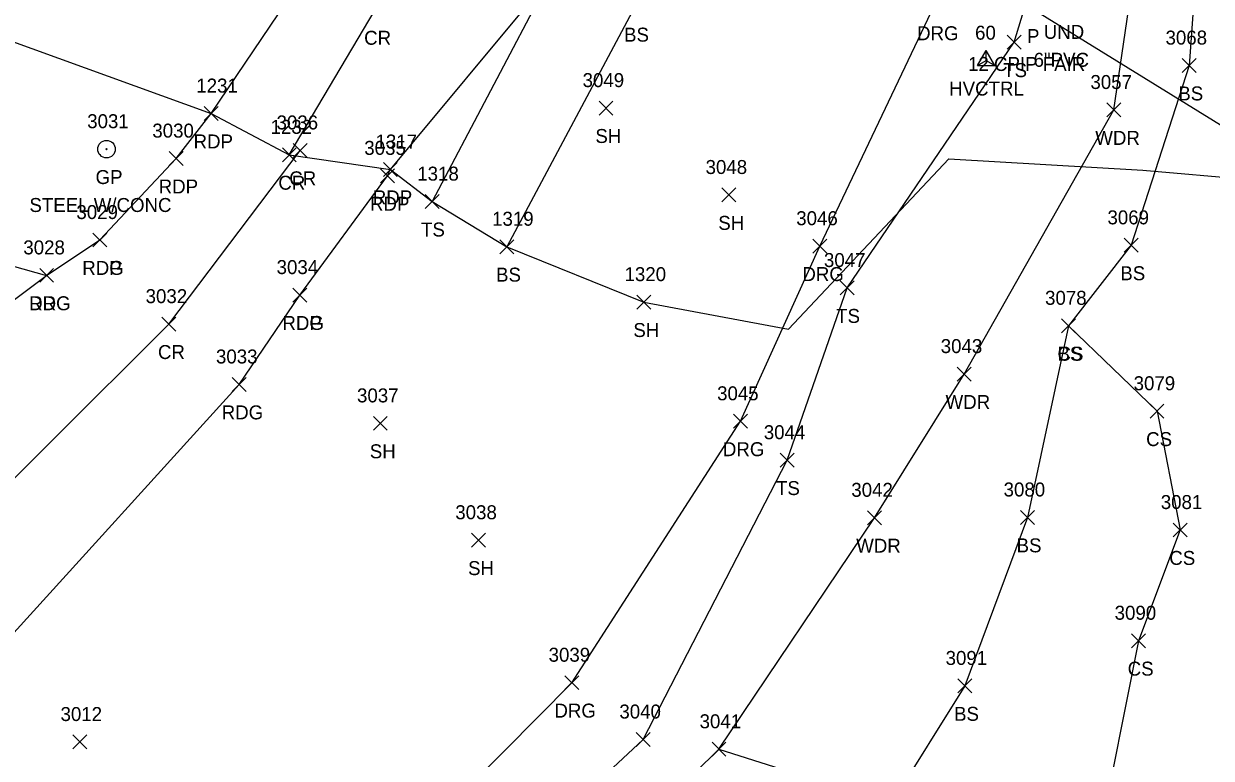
# Model space of a CAD drawing. Extents: x 49137 to 50946, y 9590 to 10709.
# Drawn here: x 49915 to 50085.1, y 9701 to 9806.1 of the extents above; entities that cross this region are included whole.
import ezdxf

# ---------------------------------------------------------------- set-up
doc = ezdxf.new("R2010")
doc.units = 0
for name, color, linetype in [('C_A', 7, 'Continuous'), ('C_I', 7, 'Continuous'), ('CPSM', 7, 'Continuous'), ('D_A', 7, 'Continuous'), ('D_C', 7, 'Continuous'), ('DCP', 7, 'Continuous'), ('L_A', 7, 'Continuous'), ('L_I', 7, 'Continuous'), ('L_TIC', 7, 'Continuous'), ('LAWA', 7, 'Continuous'), ('LELB', 7, 'Continuous'), ('LSOGP', 7, 'Continuous'), ('P_A', 7, 'Continuous'), ('P_I', 7, 'Continuous'), ('P_TIC', 7, 'Continuous'), ('PET', 7, 'Continuous'), ('PEU', 7, 'Continuous'), ('PRC', 7, 'Continuous'), ('R_A', 7, 'Continuous'), ('R_C', 7, 'Continuous'), ('R_I', 7, 'Continuous'), ('R_TIC', 7, 'Continuous'), ('RDG', 7, 'Continuous'), ('RGP', 7, 'Continuous')]:
    doc.layers.add(name, color=color, linetype=linetype)

msp = doc.modelspace()

# ---------------------------------------------------------------- linework, layer by layer
at = {"layer": 'CPSM'}
for p, q in [((50051.61, 9800.13), (50052.86, 9802.3)), ((50054.11, 9800.13), (50052.86, 9802.3)), ((50052.87, 9800.85), (50052.86, 9802.3)), ((50051.61, 9800.13), (50052.87, 9800.85)), ((50052.87, 9800.85), (50052.87, 9800.85)), ((50052.87, 9800.85), (50054.11, 9800.13)), ((50051.61, 9800.13), (50054.11, 9800.13))]:
    msp.add_line(p, q, dxfattribs=at)
at = {"layer": 'DCP'}
msp.add_lwpolyline([(49941.69, 9827.48), (50059.34, 9808.37), (50181.4, 9733.09), (50281.74, 9743.29), (50422.72, 9892.52), (50122.34, 10663.61), (50179.93, 10552.61), (50179.64, 10394.45), (50122.34, 10285.07), (50121.56, 10284.35)], dxfattribs=at)
at = {"layer": 'L_TIC'}
for points in [[(50055.89, 9802.49), (50057.89, 9804.49)], [(50057.89, 9802.49), (50055.89, 9804.49)], [(50080.95, 9799.15), (50082.95, 9801.15)], [(50082.95, 9799.15), (50080.95, 9801.15)], [(49997.39, 9793.06), (49999.39, 9795.06)], [(49999.39, 9793.06), (49997.39, 9795.06)], [(50070.14, 9792.79), (50072.14, 9794.79)], [(50072.14, 9792.79), (50070.14, 9794.79)], [(49972.48, 9779.67), (49974.48, 9781.67)], [(49974.48, 9779.67), (49972.48, 9781.67)], [(50015, 9780.62), (50017, 9782.62)], [(50017, 9780.62), (50015, 9782.62)], [(49983.2, 9773.21), (49985.2, 9775.21)], [(49985.2, 9773.21), (49983.2, 9775.21)], [(50072.64, 9773.41), (50074.64, 9775.41)], [(50074.64, 9773.41), (50072.64, 9775.41)], [(50031.96, 9767.3), (50033.96, 9769.3)], [(50033.96, 9767.3), (50031.96, 9769.3)], [(50002.82, 9765.28), (50004.82, 9767.28)], [(50004.82, 9765.28), (50002.82, 9767.28)], [(50063.64, 9761.89), (50065.64, 9763.89)], [(50065.64, 9761.89), (50063.64, 9763.89)], [(50063.64, 9761.89), (50065.64, 9763.89)], [(50065.64, 9761.89), (50063.64, 9763.89)], [(50048.69, 9754.98), (50050.69, 9756.98)], [(50050.69, 9754.98), (50048.69, 9756.98)], [(50076.34, 9749.66), (50078.34, 9751.66)], [(50078.34, 9749.66), (50076.34, 9751.66)], [(49965.06, 9747.92), (49967.06, 9749.92)], [(49967.06, 9747.92), (49965.06, 9749.92)], [(50023.34, 9742.65), (50025.34, 9744.65)], [(50025.34, 9742.65), (50023.34, 9744.65)], [(50035.88, 9734.4), (50037.88, 9736.4)], [(50037.88, 9734.4), (50035.88, 9736.4)], [(50057.78, 9734.45), (50059.78, 9736.45)], [(50059.78, 9734.45), (50057.78, 9736.45)], [(50079.65, 9732.65), (50081.65, 9734.65)], [(50081.65, 9732.65), (50079.65, 9734.65)], [(49979.14, 9731.19), (49981.14, 9733.19)], [(49981.14, 9731.19), (49979.14, 9733.19)], [(50073.7, 9716.8), (50075.7, 9718.8)], [(50075.7, 9716.8), (50073.7, 9718.8)], [(50048.82, 9710.33), (50050.82, 9712.33)], [(50050.82, 9710.33), (50048.82, 9712.33)], [(49922.01, 9702.3), (49924.01, 9704.3)], [(49924.01, 9702.3), (49922.01, 9704.3)], [(50002.73, 9702.66), (50004.73, 9704.66)], [(50004.73, 9702.66), (50002.73, 9704.66)], [(50013.58, 9701.26), (50015.58, 9703.26)], [(50015.58, 9701.26), (50013.58, 9703.26)], [(50013.58, 9701.26), (50015.58, 9703.26)], [(50015.58, 9701.26), (50013.58, 9703.26)], [(50013.58, 9701.26), (50015.58, 9703.26)], [(50015.58, 9701.26), (50013.58, 9703.26)]]:
    msp.add_lwpolyline(points, dxfattribs=at)
at = {"layer": 'LAWA'}
for points in [[(50014.58, 9702.26), (50036.88, 9735.4), (50049.69, 9755.98), (50071.14, 9793.79), (50075.59, 9824.01)], [(50014.58, 9702.26), (50039.25, 9694.43), (50057.47, 9686.03), (50059.19, 9683.38), (50066.6, 9684.8), (50067.1, 9678.81), (50060, 9674.6), (50065.38, 9669.03), (50074.52, 9675.19), (50088.42, 9676.7), (50096.85, 9701.02)]]:
    msp.add_lwpolyline(points, dxfattribs=at)
at = {"layer": 'LELB'}
for points in [[(49989.55, 9904), (49994.55, 9892.66), (49998.25, 9866.29), (49993.74, 9835.93), (49990.22, 9812.41), (49973.48, 9780.67)], [(49989.55, 9904), (50004.44, 9895.83), (50014.35, 9868.49), (50005.81, 9838.02), (50002.54, 9808.57), (49984.2, 9774.21)], [(49918.74, 9626.48), (49955.93, 9659.04), (50003.73, 9703.66), (50024.34, 9743.65), (50032.96, 9768.3), (50056.89, 9803.49), (50065.96, 9833.31)], [(50083.49, 9821.5), (50081.95, 9800.15), (50073.64, 9774.41), (50064.64, 9762.89), (50058.78, 9735.45), (50049.82, 9711.33), (50039.25, 9694.43), (50032.02, 9676.72), (50013.68, 9661.38), (49987.38, 9644.23), (49938.8, 9613.7)], [(50064.64, 9762.89), (50077.34, 9750.66), (50080.65, 9733.65), (50074.7, 9717.8), (50068.89, 9688.77)], [(49927.18, 9621.5), (49962.52, 9650.98), (50014.58, 9702.26)]]:
    msp.add_lwpolyline(points, dxfattribs=at)
at = {"layer": 'LSOGP'}
msp.add_lwpolyline([(49755.15, 9779.76), (49800.92, 9796.37), (49846.88, 9798.73), (49883.29, 9814.53), (49941.82, 9793.29), (49953.02, 9787.37), (49967.5, 9785.27), (49973.48, 9780.68), (49984.2, 9774.21), (50003.83, 9766.28), (50024.54, 9762.42), (50047.5, 9786.77), (50075.33, 9785.18), (50090.63, 9783.84), (50104.73, 9771.51), (50112.8, 9763.41), (50118.43, 9787.61), (50123.54, 9809.37), (50149.22, 9831.22), (50159.79, 9836.35), (50172.36, 9837.78), (50185.48, 9838.52)], dxfattribs=at)
at = {"layer": 'P_TIC'}
for points in [[(49940.82, 9792.28), (49942.82, 9794.28)], [(49942.82, 9792.28), (49940.82, 9794.28)], [(49952.02, 9786.37), (49954.02, 9788.37)], [(49954.02, 9786.37), (49952.02, 9788.37)], [(49953.58, 9787), (49955.58, 9789)], [(49955.58, 9787), (49953.58, 9789)], [(49935.81, 9785.83), (49937.81, 9787.83)], [(49937.81, 9785.83), (49935.81, 9787.83)], [(49966.1, 9783.36), (49968.1, 9785.36)], [(49968.1, 9783.36), (49966.1, 9785.36)], [(49966.49, 9784.27), (49968.49, 9786.27)], [(49968.49, 9784.27), (49966.49, 9786.27)], [(49924.86, 9774.17), (49926.86, 9776.17)], [(49926.86, 9774.17), (49924.86, 9776.17)], [(49924.86, 9774.17), (49926.86, 9776.17)], [(49926.86, 9774.17), (49924.86, 9776.17)], [(49917.25, 9769.11), (49919.25, 9771.11)], [(49919.25, 9769.11), (49917.25, 9771.11)], [(49953.54, 9766.29), (49955.54, 9768.29)], [(49955.54, 9766.29), (49953.54, 9768.29)], [(49953.54, 9766.29), (49955.54, 9768.29)], [(49955.54, 9766.29), (49953.54, 9768.29)], [(49934.77, 9762.13), (49936.77, 9764.13)], [(49936.77, 9762.13), (49934.77, 9764.13)], [(49944.85, 9753.49), (49946.85, 9755.49)], [(49946.85, 9753.49), (49944.85, 9755.49)]]:
    msp.add_lwpolyline(points, dxfattribs=at)
at = {"layer": 'PET'}
for points in [[(49941.82, 9793.28), (49956.36, 9814.79), (49966.07, 9820.11), (49965.86, 9838.81), (49966.08, 9865), (49966, 9911.87), (49965.71, 9947.75), (49965.49, 9981.09), (49977.22, 9981.69), (49989.03, 9982.19), (49989.41, 9973.23), (49989.05, 9951.58), (49989.55, 9915.93), (49989.55, 9904), (49989.7, 9866.37), (49989.32, 9838.09), (49989.1, 9811.29), (49967.49, 9785.27)], [(49936.81, 9786.83), (49941.82, 9793.28)], [(49925.86, 9775.17), (49936.81, 9786.83)], [(49967.1, 9784.36), (49967.49, 9785.27)], [(49954.54, 9767.29), (49967.1, 9784.36)]]:
    msp.add_lwpolyline(points, dxfattribs=at)
at = {"layer": 'PEU'}
for points in [[(49842.28, 9718.62), (49887.62, 9747.17), (49918.25, 9770.11), (49925.86, 9775.17)], [(49862.34, 9689.85), (49911.69, 9716.87), (49945.85, 9754.49), (49954.54, 9767.29)]]:
    msp.add_lwpolyline(points, dxfattribs=at)
at = {"layer": 'PRC'}
for points in [[(49953.02, 9787.37), (49965.31, 9808.12), (49973.95, 9825.62), (49977.78, 9849.57), (49977.72, 9864.78), (49978.39, 9912), (49976.86, 9948.04), (49977.22, 9981.69)], [(49852.15, 9703.48), (49901.8, 9729.33), (49935.77, 9763.13), (49954.58, 9788)]]:
    msp.add_lwpolyline(points, dxfattribs=at)
at = {"layer": 'R_TIC'}
for points in [[(50028.04, 9773.29), (50030.04, 9775.29)], [(50030.04, 9773.29), (50028.04, 9775.29)], [(49917.25, 9769.11), (49919.25, 9771.11)], [(49919.25, 9769.11), (49917.25, 9771.11)], [(50016.65, 9748.22), (50018.65, 9750.22)], [(50018.65, 9748.22), (50016.65, 9750.22)], [(49992.51, 9710.79), (49994.51, 9712.79)], [(49994.51, 9710.79), (49992.51, 9712.79)]]:
    msp.add_lwpolyline(points, dxfattribs=at)
at = {"layer": 'RDG'}
for points in [[(49907.98, 9635.82), (49950.02, 9667.9), (49993.51, 9711.79), (50017.65, 9749.22), (50029.04, 9774.29), (50045.48, 9808.77), (50053.47, 9835.1)], [(49832.87, 9731.8), (49875.88, 9755.3), (49906.47, 9773.36), (49918.25, 9770.11)]]:
    msp.add_lwpolyline(points, dxfattribs=at)
at = {"layer": 'RGP'}
msp.add_line((49926.83, 9788.18), (49926.83, 9788.18), dxfattribs=at)
for radius in [1.25, 0.0833]:
    msp.add_circle((49926.83, 9788.18), radius, dxfattribs=at)

# ---------------------------------------------------------------- texts
at = {"layer": 'C_A'}
msp.add_text('HVCTRL', height=2, dxfattribs=at).set_placement((50047.56, 9795.85))
at = {"layer": 'C_I'}
msp.add_text('60', height=2, dxfattribs=at).set_placement((50051.27, 9803.85))
at = {"layer": 'D_A'}
for s, p in [('P', (50058.71, 9803.37)), ('UND', (50061.11, 9803.97))]:
    msp.add_text(s, height=2, dxfattribs=at).set_placement(p)
at = {"layer": 'D_C'}
for s, p in [('6"PVC', (50059.66, 9799.97)), ('12 CPIP FAIR', (50050.27, 9799.37))]:
    msp.add_text(s, height=2, dxfattribs=at).set_placement(p)
at = {"layer": 'L_A'}
for s, p in [('BS', (50000.98, 9803.57)), ('TS', (50055.3, 9798.49)), ('BS', (50080.39, 9795.15)), ('SH', (49996.87, 9789.06)), ('WDR', (50068.5, 9788.79)), ('SH', (50014.48, 9776.62)), ('TS', (49971.89, 9775.67)), ('BS', (50072.08, 9769.41)), ('BS', (49982.64, 9769.21)), ('TS', (50031.37, 9763.3)), ('SH', (50002.31, 9761.28)), ('CS', (50063.08, 9757.89)), ('BS', (50063.08, 9757.89)), ('WDR', (50047.05, 9750.98)), ('CS', (50075.78, 9745.66)), ('SH', (49964.55, 9743.92)), ('TS', (50022.75, 9738.65)), ('WDR', (50034.24, 9730.4)), ('BS', (50057.22, 9730.45)), ('CS', (50079.1, 9728.65)), ('SH', (49978.63, 9727.19)), ('CS', (50073.14, 9712.8)), ('BS', (50048.26, 9706.33))]:
    msp.add_text(s, height=2, dxfattribs=at).set_placement(p)
at = {"layer": 'L_I'}
for s, p in [('3068', (50078.56, 9803.15)), ('3049', (49995.04, 9797.06)), ('3057', (50067.8, 9796.79)), ('3048', (50012.66, 9784.62)), ('1318', (49971.35, 9783.67)), ('1319', (49982.07, 9777.21)), ('3069', (50070.24, 9777.41)), ('3047', (50029.62, 9771.3)), ('1320', (50001.05, 9769.28)), ('3078', (50061.3, 9765.89)), ('3078', (50061.3, 9765.89)), ('3043', (50046.35, 9758.98)), ('3079', (50073.99, 9753.66)), ('3037', (49962.72, 9751.92)), ('3044', (50021, 9746.65)), ('3042', (50033.54, 9738.4)), ('3080', (50055.36, 9738.45)), ('3081', (50077.88, 9736.65)), ('3038', (49976.8, 9735.19)), ('3090', (50071.27, 9720.8)), ('3091', (50047.05, 9714.33)), ('3012', (49920.24, 9706.3)), ('3040', (50000.31, 9706.66)), ('3041', (50011.8, 9705.26)), ('3041', (50011.8, 9705.26)), ('3041', (50011.8, 9705.26))]:
    msp.add_text(s, height=2, dxfattribs=at).set_placement(p)
at = {"layer": 'P_A'}
for s, p in [('CR', (49963.74, 9803.12)), ('RDP', (49939.3, 9788.28)), ('CR', (49953.01, 9783)), ('RDP', (49934.3, 9781.83)), ('CR', (49951.45, 9782.37)), ('RDP', (49964.98, 9780.27)), ('RDP', (49964.58, 9779.36)), ('RDG', (49923.35, 9770.17)), ('RDP', (49923.35, 9770.17)), ('RDG', (49915.74, 9765.11)), ('RDG', (49952.03, 9762.29)), ('RDP', (49952.03, 9762.29)), ('CR', (49934.2, 9758.13)), ('RDG', (49943.33, 9749.49))]:
    msp.add_text(s, height=2, dxfattribs=at).set_placement(p)
at = {"layer": 'P_I'}
for s, p in [('1231', (49939.69, 9796.28)), ('3030', (49933.39, 9789.83)), ('1232', (49950.33, 9790.37)), ('3036', (49951.19, 9791)), ('1317', (49965.37, 9788.27)), ('3035', (49963.76, 9787.36)), ('3029', (49922.51, 9778.17)), ('3029', (49922.51, 9778.17)), ('3028', (49914.91, 9773.11)), ('3034', (49951.2, 9770.29)), ('3034', (49951.2, 9770.29)), ('3032', (49932.43, 9766.13)), ('3033', (49942.51, 9757.49))]:
    msp.add_text(s, height=2, dxfattribs=at).set_placement(p)
at = {"layer": 'R_A'}
for s, p in [('DRG', (50042.96, 9803.77)), ('GP', (49925.26, 9783.18)), ('DRG', (50026.53, 9769.29)), ('DRG', (49915.74, 9765.11)), ('DRG', (50015.14, 9744.22)), ('DRG', (49991, 9706.79))]:
    msp.add_text(s, height=2, dxfattribs=at).set_placement(p)
at = {"layer": 'R_C'}
msp.add_text('STEEL W/CONC', height=2, dxfattribs=at).set_placement((49915.78, 9779.18))
at = {"layer": 'R_I'}
for s, p in [('3031', (49924.06, 9791.18)), ('3046', (50025.65, 9777.29)), ('3028', (49914.91, 9773.11)), ('3045', (50014.31, 9752.22)), ('3039', (49990.17, 9714.79))]:
    msp.add_text(s, height=2, dxfattribs=at).set_placement(p)

doc.saveas('drawing.dxf')
